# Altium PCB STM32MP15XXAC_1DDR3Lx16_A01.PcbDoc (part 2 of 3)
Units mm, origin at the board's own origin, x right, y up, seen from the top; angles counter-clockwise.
Board outline 89 x 120 mm, 4 copper layers (Top Layer, Signal Layer 1, Signal Layer 2, Bottom Layer), stack 1.571 mm thick; 133 components, 92 nets, 915 pads, 400 vias.
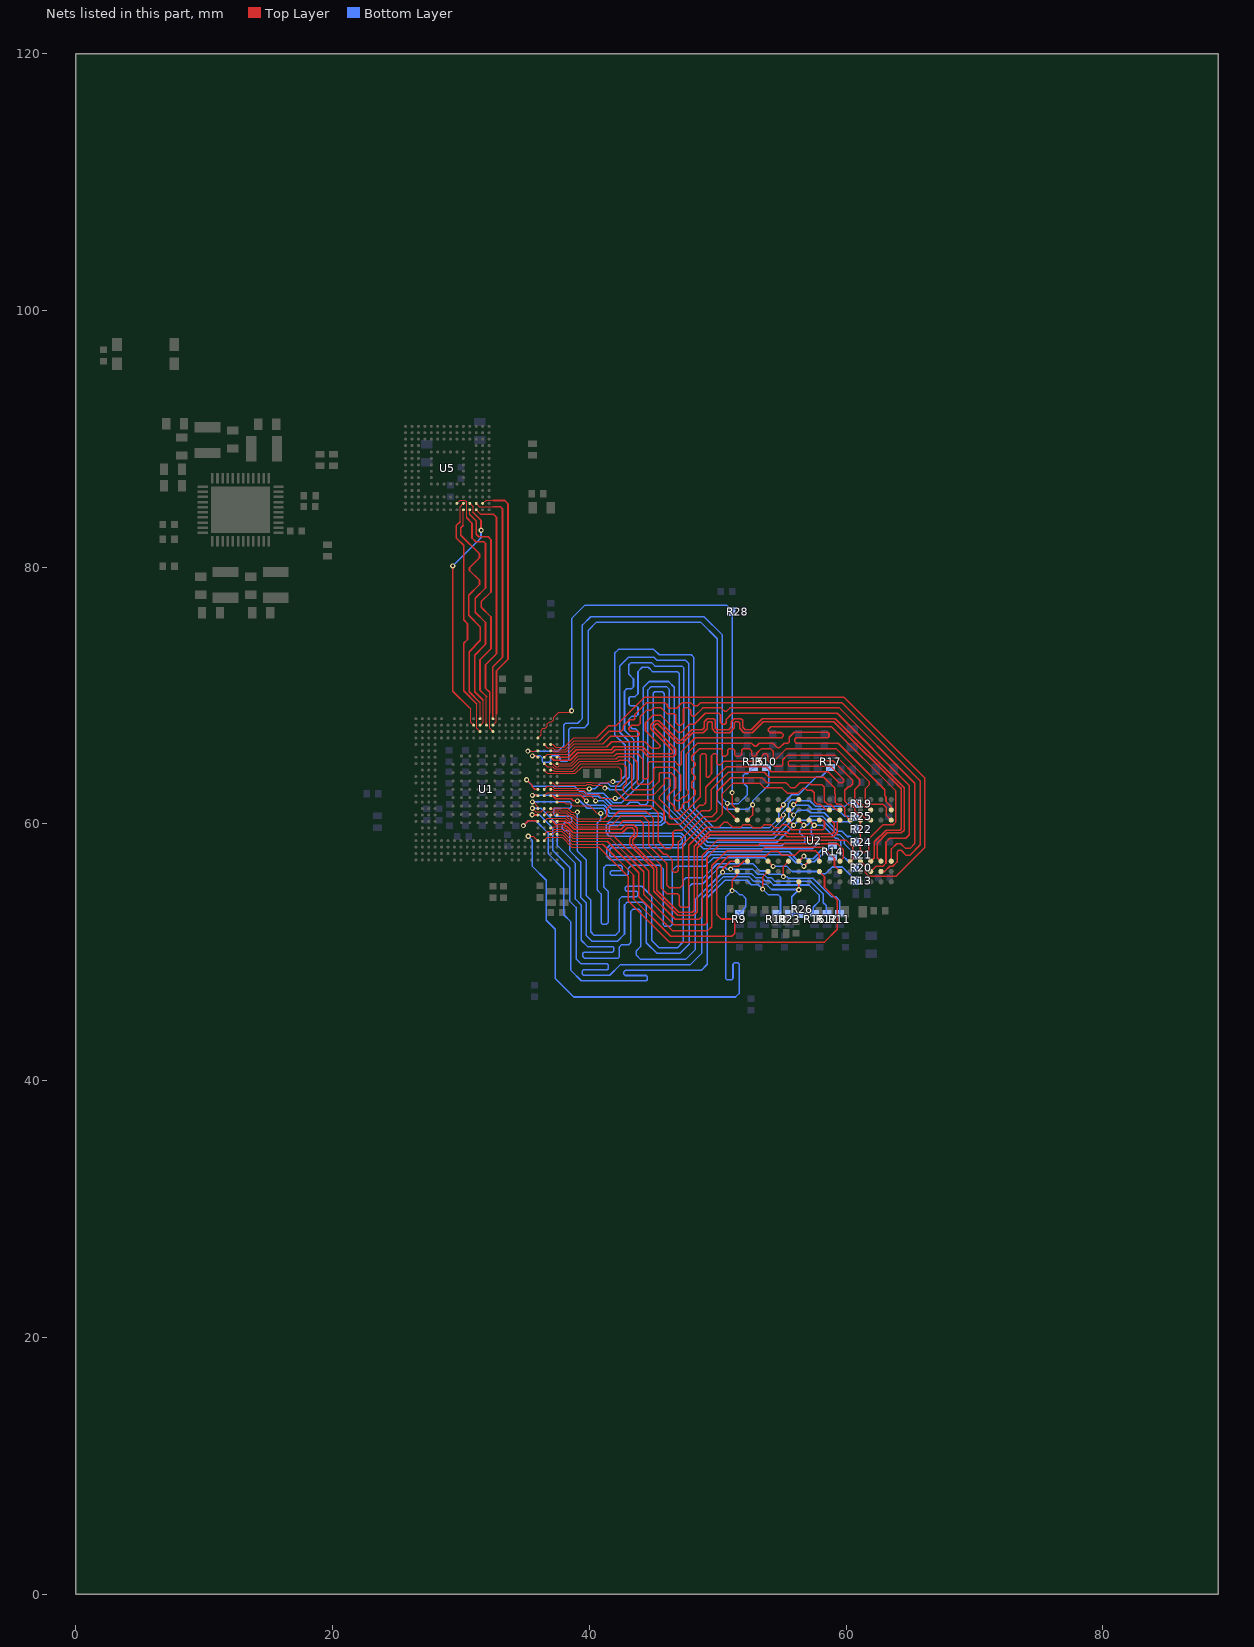
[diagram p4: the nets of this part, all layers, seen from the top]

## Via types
v1: diameter 0.4, hole 0.2, Top Layer to Bottom Layer, tented both sides, 241 vias
v2: diameter 0.6, hole 0.3, Top Layer to Bottom Layer, tented both sides, 81 vias
v3: diameter 0.25, hole 0.1, Top Layer to Signal Layer 1, tented top, 72 vias
v4: diameter 0.25, hole 0.1, Top Layer to Signal Layer 1, tented both sides, 6 vias

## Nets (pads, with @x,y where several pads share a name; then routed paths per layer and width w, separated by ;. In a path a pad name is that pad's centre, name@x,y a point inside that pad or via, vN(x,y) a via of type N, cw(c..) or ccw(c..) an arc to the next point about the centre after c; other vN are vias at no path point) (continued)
DDR_A8: R9.1 U1.Y20 U2.T8 | length 44.1
  Top Layer w0.09: v1(35.25,59.05) 35.65,59.05 U1.Y20@36,58.7
  Top Layer w0.12: v1(51.135,54.81) 51.135,55.634 51.525,56.024 U2.T8@51.525,56.3
  Bottom Layer w0.12: v1(35.25,59.05) 35.55,58.75 35.55,56.725 36.65,55.625 36.65,52.5 37.35,51.8 37.35,47.975 38.8,46.525 51.4,46.525 51.675,46.8 51.675,49.1 51.575,49.2 51.325,49.2 51.2,49.075 51.2,47.975 51.1,47.875 50.725,47.875 50.625,47.975 50.625,54.3 51.045,54.72 v1(51.135,54.81) 51.39,54.81 51.7,54.5 51.9,54.5 52.2,54.2 52.2,53.54 R9.1@51.705,53.045 R9.1@51.555,53.195
DDR_A9: R10.1 U1.G20 U2.R3 | length 47.2
  Top Layer w0.12: v1(35.575,65.3) 35.9,65.3 U1.G20@36,65.2 ; U2.R3@52.325,60.3 52.725,60.7 v1(52.725,61.5)
  Bottom Layer w0.12: v1(35.575,65.3) 36.2,65.3 36.325,65.175 36.325,64.9 36.4,64.825 36.9,64.825 37,64.925 37,65.225 37.1,65.325 37.6,65.325 37.725,65.2 37.725,64.975 37.825,64.875 38.25,64.875 38.4,65.025 38.4,67.35 38.55,67.5 39.625,67.5 39.925,67.8 39.925,75.075 40.575,75.725 48.675,75.725 49.975,74.425 49.975,61.825 50.65,61.15 52.375,61.15 v1(52.725,61.5) 52.725,61.79 54,63.065 54,64.2 R10.1@53.8,64.4
DDR_A10: R11.1 U1.R22 U2.L7 | length 49.9
  Top Layer w0.09: U1.R22@37,61.2 37.169,61.2 37.249,61.28 37.8,61.28 37.87,61.21 38.34,61.21 38.625,60.925 v1(39.075,60.925)
  Top Layer w0.12: v1(55.125,55.9) 55.125,56.7 U2.L7@55.525,57.1
  Bottom Layer w0.12: v1(39.075,60.925) 39.075,57.9 39.775,57.2 39.775,54.425 40.125,54.075 40.125,51.6 40.4,51.325 42.025,51.325 42.325,51.625 42.325,54.125 42.55,54.35 43.7,54.35 43.8,54.45 43.8,54.65 43.7,54.75 42.9,54.75 42.8,54.85 42.8,55.05 42.9,55.15 44.1,55.15 44.875,54.375 44.875,50.925 45.45,50.35 46.85,50.35 47.325,50.825 47.325,55.6 47.55,55.825 48.9,55.825 49.975,56.9 52.75,56.9 53.31,56.34 53.735,56.34 54,56.075 54.95,56.075 v1(55.125,55.9) 55.4,55.9 55.525,55.775 57.425,55.775 58.875,54.325 59.205,54.325 59.53,54 59.53,53.12 R11.1@59.455,53.045
DDR_A11: R12.1 U1.R20 U2.R7 | length 52.1
  Top Layer w0.09: v1(35.575,61.725) 35.636,61.725 36,61.361 U1.R20@36,61.2
  Top Layer w0.12: v1@51.015,56.42 v1@51.015,56.424 ; v1(51.015,56.49) 51.245,56.72 51.654,56.72 52.034,57.1 U2.R7@52.325,57.1
  Bottom Layer w0.12: v1(35.575,61.725) 38.475,61.725 38.6,61.6 38.6,61.325 38.5,61.225 37.325,61.225 37.225,61.125 37.225,60.775 37.4,60.6 38.525,60.6 38.65,60.475 38.65,60.2 38.55,60.1 38.075,60.1 37.9,59.925 37.9,59.65 38.075,59.475 38.375,59.475 38.5,59.35 38.5,57.9 39.35,57.05 39.35,54.275 39.775,53.85 39.775,51.325 40.225,50.875 42.2,50.875 42.75,51.425 42.75,53.7 42.95,53.9 44.2,53.9 44.45,53.65 44.45,50.75 45.275,49.925 47.075,49.925 47.8,50.65 47.8,55.125 48.025,55.35 48.85,55.35 50.15,56.65 50.55,56.65 50.71,56.49 v1(51.015,56.49) 52.71,56.49 53.125,56.075 53.6,56.075 53.85,55.825 54.175,55.825 54.475,55.525 57.25,55.525 58.23,54.545 58.23,53.87 58.455,53.645 R12.1@58.455,53.045
DDR_A12: R13.1 U1.P23 U2.N7 | length 51.2
  Top Layer w0.09: U1.P23@37.5,61.7 38.075,61.7 38.2,61.575 38.575,61.575 38.71,61.44 40.048,61.44 40.52,60.968 40.52,60.93 40.625,60.825 v1(40.9,60.825)
  Top Layer w0.12: U2.N7@53.925,57.1 v1(54.325,56.7)
  Bottom Layer w0.12: v1(40.9,60.825) 40.9,60.35 40.625,60.075 40.625,54.85 40.925,54.55 40.925,52.3 41.05,52.175 41.325,52.175 41.475,52.325 41.475,54.75 41.125,55.1 41.125,56.6 41.3,56.775 42.475,56.775 42.575,56.675 42.575,56.475 42.475,56.375 41.75,56.375 41.65,56.275 41.65,56.1 41.75,56 42.925,56 43.05,56.125 43.05,56.55 43.275,56.775 45.5,56.775 45.75,56.525 45.75,52.175 45.9,52.025 46.325,52.025 46.45,52.15 46.45,56.375 46.8,56.725 49.025,56.725 49.675,57.375 53.65,57.375 54.18,56.845 v1(54.325,56.7) 55.4,56.7 55.8,56.3 57.75,56.3 57.925,56.125 58.4,56.125 58.925,56.65 59.7,56.65 R13.1@60.755,55.595
DDR_A13: R15.1 U1.F20 U2.T3 | length 45.6
  Top Layer w0.09: v1(35.225,65.675) 35.25,65.7 35.437,65.7 35.482,65.655 35.768,65.655 35.813,65.7 U1.F20@36,65.7
  Top Layer w0.12: v1(50.765,61.61) 50.765,61.06 U2.T3@51.525,60.3
  Bottom Layer w0.09: v1(35.225,65.675) 35.245,65.655 35.92,65.655
  Bottom Layer w0.12: 35.92,65.655 37.555,65.655 38,66.1 38,67.7 38.15,67.85 39.1,67.85 39.475,68.225 39.475,75.5 40.125,76.15 48.95,76.15 50.35,74.75 50.35,62.025 v1(50.765,61.61) ; v1@50.665,61.59 51.625,61.59 52.3,62.265 52.3,62.9 52,63.2 52,63.8 52.1,63.9 52.3,63.9 R15.1@52.8,64.4
DDR_A14: R16.1 U1.R21 U2.T7 | length 54.1
  Top Layer w0.09: 35.725,61.075 35.85,60.95 36.25,60.95 U1.R21@36.5,61.2
  Top Layer w0.12: v1(50.395,56.25) 50.395,56.51 50.985,57.1 U2.T7@51.525,57.1
  Bottom Layer w0.12: v1(35.575,61.225) 36.25,61.225 37.525,59.95 37.525,58.325 38.925,56.925 38.925,54.15 39.375,53.7 39.375,50.95 39.875,50.45 41.85,50.45 41.925,50.375 41.925,50.125 41.825,50.025 39.6,50.025 39.5,49.925 39.5,49.675 39.625,49.55 42.25,49.55 42.35,49.65 42.35,50.425 42.525,50.6 43.075,50.6 43.225,50.75 43.225,53.175 43.425,53.375 43.85,53.375 44,53.225 44,50.45 43.675,50.125 43.675,49.775 44,49.45 47.5,49.45 48.275,50.225 48.275,54.13 v1(50.395,56.25) 50.52,56.125 52.65,56.125 52.95,55.825 53.425,55.825 53.675,55.575 54.025,55.575 54.35,55.25 57.125,55.25 57.905,54.47 57.905,53.97 57.455,53.52 R16.1@57.455,53.045
DDR_BA0: R17.1 U1.L23 U2.M2 | length 48
  Top Layer w0.09: U1.L23@37.5,63.2 39.697,63.2 39.762,63.265 40.188,63.265 40.253,63.2 41.4,63.2 41.5,63.3 v1(41.85,63.3)
  Top Layer w0.12: U2.M2@54.725,61.1 v1(55.125,61.5)
  Bottom Layer w0.12: v1(41.85,63.3) 42.35,63.3 42.8,63.75 42.8,66.125 41.975,66.95 41.975,73.3 42.275,73.6 45.025,73.6 45.45,73.175 47.95,73.175 48.125,73 48.125,61.3 49.7,59.725 54.05,59.725 54.75,60.425 54.75,60.975 55.125,61.35 v1(55.125,61.5) 55.125,61.625 55.775,62.275 56.3,62.275 57.7,63.675 58.075,63.675 R17.1@58.8,64.4
DDR_BA1: R18.1 U1.U20 U2.N8 | length 45.5
  Top Layer w0.12: v1(34.875,59.875) 35.26,60.26 35.749,60.26 35.809,60.2 U1.U20@36,60.2 ; v1@53.505,54.939 53.505,55.88 U2.N8@53.925,56.3
  Bottom Layer w0.12: v1(34.875,59.875) 35.26,60.26 35.84,60.26 36.8,59.3 36.8,57.7 38.025,56.475 38.025,52.925 38.575,52.375 38.575,48.6 39.375,47.8 44.45,47.8 44.525,47.875 44.525,48.125 44.45,48.2 42.8,48.2 42.7,48.3 42.7,48.5 42.8,48.6 48.725,48.6 49.2,49.075 49.2,54.25 50.575,55.625 52.275,55.625 52.625,55.275 53.16,55.275 v1(53.505,54.93) 53.935,54.5 54.7,54.5 54.9,54.3 54.9,53.24 R18.1@54.705,53.045
DDR_BA2: R19.1 U1.M21 U2.M3 | length 49.6
  Top Layer w0.09: U1.M21@36.5,62.7 36.75,62.95 37.135,62.95 37.295,62.79 39.885,62.79 39.95,62.725 v1@40,62.725
  Top Layer w0.12: U2.M3@54.725,60.3 v1@55.105,60.68
  Bottom Layer w0.12: v1(40,62.735) 40.435,62.735 40.875,63.175 41.466,63.175 41.701,62.94 41.999,62.94 42.005,62.945 ; 42,62.95 42.425,62.95 43.125,63.65 43.125,66.4 42.375,67.15 42.375,72.3 43.075,73 45.025,73 45.275,72.75 47.5,72.75 47.75,72.5 47.75,61.225 49.55,59.425 54.125,59.425 55.125,60.425 v1(55.125,60.7) 55.125,60.925 55.5,61.3 55.5,61.6 55.8,61.9 56.1,61.9 56.18,61.82 57.18,61.82 57.6,61.4 59.955,61.4 60.225,61.67 60.68,61.67 R19.1@60.755,61.595
DDR_CASN: R21.1 U1.N20 U2.K3 | length 49.6
  Top Layer w0.09: v1(35.575,62.225) v1@35.6,62.2
  Top Layer w0.12: v1(35.575,62.225) 35.975,62.225 U1.N20@36,62.2 ; U2.K3@56.325,60.3 v1(56.725,59.9)
  Bottom Layer w0.12: v1(35.575,62.225) 39.375,62.225 39.435,62.165 40.71,62.165 40.825,62.05 41.169,62.05 41.794,61.425 42.875,61.425 43.15,61.7 43.8,61.7 44,61.5 44.4,61.5 44.575,61.675 44.575,70.441 44.834,70.7 46.016,70.7 46.25,70.466 46.25,61.175 49.125,58.3 55,58.3 55.2,58.5 56.7,58.5 56.8,58.6 56.8,58.9 56.4,59.3 56.4,59.575 v1(56.725,59.9) 56.975,59.9 57.375,60.3 58.175,60.3 59.325,59.15 59.53,59.15 59.88,58.8 59.88,58.445 60.73,57.595 R21.1@60.755,57.595
DDR_CKE: R23.1 R26.2 U1.T20 U2.K9 | length 45.4
  Top Layer w0.12: v1(35.55,60.725) 35.575,60.7 U1.T20@36,60.7 ; v1(56.325,54.88) U2.K9@56.325,55.5
  Bottom Layer w0.12: v1(35.55,60.725) 36.125,60.725 37.15,59.7 37.15,57.95 38.475,56.625 38.475,54 38.975,53.5 38.975,49.5 39.35,49.125 41.375,49.125 41.475,49.025 41.475,48.725 41.4,48.65 39.55,48.65 39.45,48.55 39.45,48.325 39.55,48.225 41.6,48.225 42.4,49.025 47.85,49.025 48.775,49.95 48.775,54.225 50.425,55.875 52.475,55.875 52.8,55.55 53.325,55.55 53.55,55.325 53.775,55.325 54.2,54.9 56.305,54.9 v1(56.325,54.88) 55.78,54.335 R23.1@55.78,53.045 ; R23.1@55.705,53.045 R23.1@55.78,53.045 ; R26.2@56.58,52.92 56.455,53.045 R23.1@55.78,53.045
DDR_CLK_N: R14.2 U1.N23 U2.K7 | length 46.7
  Top Layer w0.1: U1.N23@37.5,62.2 39.375,62.2 v1(39.775,61.8) ; U2.K7@56.325,57.1 v1(56.725,57.5)
  Bottom Layer w0.1: v1(39.775,61.8) 39.775,61.625 39.95,61.45 41.17,61.45 41.53,61.09 41.53,60.92 41.6,60.85 45.625,60.85 45.905,60.57 45.905,60.18 45.62,59.895 41.645,59.895 41.555,59.805 41.555,59.395 41.675,59.275 47.175,59.275 47.475,58.975 47.475,58.45 47.175,58.15 41.725,58.15 41.605,58.03 41.605,57.57 41.725,57.45 48.95,57.45 49.325,57.825 55.575,57.825 56.175,57.225 56.45,57.225 56.65,57.425 v1(56.725,57.5) 56.94,57.285 57.435,57.285 58.125,57.975 58.56,57.975 58.88,58.295 R14.2@58.955,58.295
DDR_CLK_P: R14.1 U1.N22 U2.J7 | length 47.3
  Top Layer w0.1: U1.N22@37,62.2 37.15,62.2 37.4,61.95 37.605,61.95 37.625,61.97 38.605,61.97 38.775,61.8 v1(39.075,61.8) ; v1(56.725,56.7) U2.J7@57.125,57.1
  Bottom Layer w0.1: v1(39.075,61.8) 39.275,61.8 39.855,61.22 41.075,61.22 41.3,60.995 41.3,60.825 41.505,60.62 45.53,60.62 45.675,60.475 45.675,60.275 45.525,60.125 41.55,60.125 41.325,59.9 41.325,59.3 41.58,59.045 47.08,59.045 47.245,58.88 47.245,58.545 47.08,58.38 41.63,58.38 41.375,58.125 41.375,57.475 41.63,57.22 49.045,57.22 49.42,57.595 55.48,57.595 56.1,56.975 56.45,56.975 56.58,56.845 v1(56.725,56.7) 57.08,57.055 57.53,57.055 58.215,57.74 58.56,57.74 58.905,57.395 R14.1@58.955,57.395
DDR_CSN: R22.1 U1.M22 U2.L2 | length 49.2
  Top Layer w0.09: U1.M22@37,62.7 37.145,62.7 37.225,62.62 39.567,62.62 39.857,62.33 40.695,62.33 41.025,62 v1(42.025,62)
  Top Layer w0.12: U2.L2@55.525,61.1 v1(55.925,60.7)
  Bottom Layer w0.12: v1(42.025,62) 42.35,62 43.8,63.45 43.8,67.225 43.6,67.425 43.35,67.425 43.1,67.675 43.1,68.175 43.3,68.375 43.65,68.375 43.8,68.525 43.8,69.075 43.675,69.2 43.225,69.2 43.1,69.325 43.1,69.825 43.2,69.925 43.575,69.925 43.8,70.15 43.8,71.875 44.125,72.2 44.6,72.2 44.925,71.875 46.85,71.875 47.025,71.7 47.025,61.125 49.275,58.875 54.375,58.875 55.925,60.425 v1(55.925,60.7) 56.3,61.075 57.025,61.075 57.225,60.875 58.3,60.875 58.987,60.187 60.162,60.187 R22.1@60.755,59.595
DDR_DQ0: U1.E22 U2.D7 | length 45.6
  Top Layer w0.09: U1.E22@37,66.2 37.15,66.2 37.39,65.96 38.06,65.96 38.8,66.7 40.55,66.7
  Top Layer w0.12: 40.55,66.7 41.51,67.66 42.085,67.66 44.305,69.88 59.837,69.88 66.15,63.567 66.15,58.196 63.874,55.92 61.796,55.92 61.503,56.213 61.503,56.744 61.148,57.1 U2.D7@61.125,57.1
DDR_DQ1: U1.F22 U2.A7 | length 45.3
  Top Layer w0.09: U1.F22@37,65.7 37.169,65.7 37.249,65.62 38.22,65.62 38.85,66.25 41.075,66.25
  Top Layer w0.12: 41.075,66.25 41.645,66.82 43.795,66.82 43.9,66.925 43.9,67.064 43.739,67.225 43.2,67.225 43.075,67.35 43.075,67.456 43.319,67.7 43.84,67.7 43.965,67.825 43.965,68.346 44.494,68.875 44.825,68.875 44.99,69.04 45.609,69.04 46.049,68.6 46.65,68.6 46.749,68.501 46.749,67.9 46.975,67.675 47.134,67.675 47.342,67.883 47.342,68.958 47.424,69.04 47.725,69.04 47.9,68.865 47.9,68.525 48.023,68.402 48.223,68.402 48.861,69.04 50.274,69.04 50.519,68.794 50.721,68.794 50.966,69.04 59.489,69.04 65.355,63.174 65.355,58.48 64.975,58.1 64.635,58.1 64.265,58.47 63.945,58.47 63.535,58.06 U2.A7@63.535,57.1
DDR_DQ2: U1.H21 U2.A3 | length 45.7
  Top Layer w0.09: U1.H21@36.5,64.7 36.75,64.45 37.17,64.45 37.33,64.29 38.69,64.29 39.275,64.875 42.225,64.875
  Top Layer w0.12: 42.225,64.875 42.325,64.975 42.936,64.975 43.32,64.591 43.32,62.775 43.41,62.685 44.823,62.685 45.44,63.302 45.44,63.91 45.525,63.995 46.374,63.995 46.72,63.649 46.72,62.776 46.097,62.153 46.097,61.91 46.665,61.342 46.665,61.1 46.74,61.025 46.968,61.025 47.243,61.3 47.243,61.474 47.459,61.691 47.634,61.691 48.24,62.297 48.24,62.625 47.995,62.87 47.995,63.25 48.24,63.495 48.24,63.725 47.995,63.97 47.995,64.275 48.24,64.52 48.24,64.755 47.995,65 47.995,65.269 48.601,65.875 50.25,65.875 50.37,65.755 50.37,65.37 50.45,65.29 50.64,65.29 50.775,65.425 50.775,65.75 50.9,65.875 51.2,65.875 51.325,65.75 51.325,65.39 51.425,65.29 51.74,65.29 51.875,65.425 51.875,65.775 51.975,65.875 52.475,65.875 52.65,65.7 52.65,65.4 52.76,65.29 52.95,65.29 53.055,65.395 53.055,65.504 53.426,65.875 54.125,65.875 54.325,65.675 54.325,65.175 54.4,65.1 54.587,65.1 55.362,65.875 59.231,65.875 61.8,63.306 61.8,63.04 61.485,62.725 61.485,61.831 61.776,61.54 62.887,61.54 63.125,61.302 63.125,60.7 U2.A3@63.525,60.3
DDR_DQ3: U1.E21 U2.B8 | length 44.1
  Top Layer w0.09: U1.E21@36.5,66.2 36.75,65.95 37.16,65.95 37.32,65.79 38.14,65.79 38.825,66.475 40.8,66.475
  Top Layer w0.12: 40.8,66.475 41.565,67.24 42.495,67.24 42.655,67.4 42.655,67.63 43.15,68.125 43.47,68.125 43.545,68.2 43.545,68.52 44.485,69.46 45.9,69.46 46.075,69.285 46.075,69.168 46.223,69.02 46.81,69.02 47.25,69.46 47.899,69.46 48.154,69.204 48.431,69.204 48.687,69.46 59.663,69.46 65.775,63.348 65.775,58.375 64.975,57.575 64.675,57.575 64.3,57.95 64.1,57.95 63.975,57.825 63.975,57.041 63.644,56.71 63.415,56.71 63.005,56.3 U2.B8@62.725,56.3
DDR_DQ4: U1.J21 U2.C3 | length 46.2
  Top Layer w0.09: U1.J21@36.5,64.2 36.75,63.95 38.925,63.95 39.45,64.475 42.248,64.475 42.48,64.243
  Top Layer w0.12: 42.48,64.243 42.48,63.355 42.05,62.925 42.05,62.6 42.805,61.845 44.974,61.845 45.825,60.994 45.825,60.351 46.201,59.975 47.106,59.975 48.576,61.445 48.87,61.445 49.08,61.655 49.08,62.858 50.67,64.448 51.95,64.448 ; 51.95,64.45 53.801,64.45 54.181,64.07 58.605,64.07 59.475,63.2 59.7,63.2 59.825,63.325 59.825,63.475 58.8,64.5 55.6,64.5 55.5,64.6 55.5,64.825 55.6,64.925 58.993,64.925 60.534,63.384 60.534,63.133 60.311,62.91 60.176,62.91 59.9,62.634 59.9,61.785 60.2,61.485 60.449,61.485 60.685,61.249 60.685,61.031 61.056,60.66 61.274,60.66 61.485,60.449 61.485,60.44 61.494,60.44 61.634,60.3 U2.C3@61.925,60.3
DDR_DQ5: U1.J22 U2.C2 | length 45.2
  Top Layer w0.09: U1.J22@37,64.2 37.18,64.2 37.26,64.12 38.795,64.12 39.35,64.675 42.642,64.675 42.775,64.542
  Top Layer w0.12: 42.775,64.542 42.9,64.417 42.9,63.181 42.634,62.916 42.634,62.609 42.979,62.265 44.997,62.265 45.86,63.128 45.86,63.485 45.95,63.575 46.2,63.575 46.3,63.475 46.3,62.95 45.444,62.094 45.444,61.969 46.245,61.168 46.245,60.525 46.375,60.395 46.932,60.395 48.66,62.123 48.66,65.34 48.775,65.455 49.02,65.455 49.1,65.375 49.1,63.725 49.189,63.636 49.264,63.636 ; 49.275,63.647 49.525,63.897 49.525,65.33 49.65,65.455 49.87,65.455 49.95,65.375 49.95,64.7 50.025,64.625 50.253,64.625 50.498,64.87 53.325,64.87 53.475,65.02 53.475,65.33 53.6,65.455 53.825,65.455 53.905,65.375 53.905,64.94 54.355,64.49 54.975,64.49 55.08,64.595 55.08,64.999 55.451,65.37 59.142,65.37 61.065,63.447 61.065,63.07 60.695,62.7 60.695,61.821 60.976,61.54 61.23,61.54 61.23,61.535 61.445,61.32 61.705,61.32 U2.C2@61.925,61.1
DDR_DQ6: U1.H22 U2.A2 | length 46.3
  Top Layer w0.09: U1.H22@37,64.7 37.161,64.7 37.401,64.46 37.599,64.46 37.669,64.53 38.655,64.53 39.2,65.075 42.1,65.075
  Top Layer w0.12: 42.1,65.075 42.25,65.225 43.325,65.225 43.74,64.81 43.74,63.19 43.825,63.105 44.649,63.105 45.02,63.476 45.02,64.285 45.15,64.415 46.548,64.415 47.14,63.823 47.14,62.602 46.675,62.138 46.675,61.925 46.776,61.825 47,61.825 47.288,62.112 47.462,62.112 47.723,62.374 47.723,62.548 47.575,62.696 47.575,65.443 48.427,66.295 52.649,66.295 52.894,66.05 53.007,66.05 53.252,66.295 54.299,66.295 54.644,65.95 54.843,65.95 55.188,66.295 55.475,66.295 55.575,66.395 55.575,66.75 55.975,67.15 58.6,67.15 58.675,67.075 58.675,66.8 58.6,66.725 56.125,66.725 56,66.6 56,66.425 56.13,66.295 59.405,66.295 63.025,62.675 63.025,62.2 63.115,62.11 63.115,61.76 63.525,61.35 U2.A2@63.525,61.1
DDR_DQ7: U1.G21 U2.C8 | length 46.6
  Top Layer w0.09: U1.G21@36.5,65.2 36.74,65.44 38.315,65.44 38.9,66.025 41.375,66.025
  Top Layer w0.12: 41.375,66.025 41.75,66.4 44.355,66.4 44.87,65.885 45.375,65.885 45.535,66.045 45.535,66.11 44.385,67.26 44.385,67.885 44.955,68.455 45.6,68.455 46.894,67.161 47.214,67.161 47.818,67.765 48.18,67.765 49.035,68.62 50.1,68.62 50.225,68.495 50.225,67.9 50.36,67.765 50.55,67.765 50.665,67.88 50.665,68.145 51.14,68.62 59.315,68.62 64.935,63 64.935,59.17 64.655,58.89 63.4,58.89 63.115,58.605 63.115,56.96 62.855,56.7 62.325,56.7 U2.C8@61.925,56.3
DDR_DQ8: U1.T21 U2.E3 | length 34.2
  Top Layer w0.09: U1.T21@36.5,60.7 36.75,60.95 37.16,60.95 37.32,61.11 37.73,61.11 37.8,61.04 38.27,61.04 38.555,60.755 38.72,60.755 39.075,60.4 41.15,60.4
  Top Layer w0.12: 41.15,60.4 41.375,60.625 41.375,61.175 41.625,61.425 44.8,61.425 45.375,60.85 45.375,58.65 45.95,58.075 46.3,58.075 46.525,58.3 46.525,59.375 46.675,59.525 47.25,59.525 48.75,61.025 49.35,61.025 49.5,61.175 49.5,62.684 50.844,64.028 53.628,64.028 54.007,63.65 58.27,63.65 59.12,62.8 59.12,62.39 59.145,62.365 59.145,61.71 59.315,61.54 59.609,61.54 59.915,61.234 59.915,60.71 U2.E3@60.325,60.3
DDR_DQ9: U1.U21 U2.H3 | length 35
  Top Layer w0.09: U1.U21@36.5,60.2 36.75,60.45 38.138,60.45 38.343,60.245 38.465,60.245 38.91,59.8 42.2,59.8
  Top Layer w0.12: 42.2,59.8 42.65,60.25 44,60.25 44.225,60.025 44.225,58.175 45.625,56.775 45.625,55 46.075,54.55 46.9,54.55 47,54.45 47,53.675 47.15,53.525 47.675,53.525 47.75,53.6 47.75,58.35 49.15,59.75 50.1,59.75 50.475,60.125 50.775,60.125 51.15,59.75 51.8,59.75 51.979,59.929 52.525,59.929 52.729,59.725 53.4,59.725 53.604,59.929 54.2,59.929 54.404,59.725 54.85,59.725 55.054,59.929 55.387,59.929 55.776,59.54 58.19,59.54 58.325,59.675 58.325,60.175 58.225,60.275 57.95,60.275 U2.H3@57.925,60.3
DDR_DQ10: U1.T22 U2.F2 | length 34.1
  Top Layer w0.09: U1.T22@37,60.7 37.15,60.7 37.39,60.94 37.599,60.94 37.669,60.87 38.199,60.87 38.484,60.585 38.64,60.585 39.025,60.2 41.5,60.2
  Top Layer w0.12: 41.5,60.2 42.3,61 44.425,61 45,60.425 45,58.45 45.8,57.65 46.025,57.65 46.45,57.225 46.45,56.4 46.6,56.25 46.8,56.25 46.95,56.4 46.95,58.6 48.925,60.575 49.575,60.575 49.925,60.925 49.925,62.515 51.015,63.605 53.451,63.605 ; 53.454,63.608 53.833,63.23 55.305,63.23 55.725,62.81 56.015,62.81 56.4,63.195 57.154,63.195 57.299,63.05 58.139,63.05 58.315,62.874 58.315,61.77 58.555,61.53 58.819,61.53 59.249,61.1 U2.F2@59.525,61.1
DDR_DQ11: U1.W21 U2.F7 | length 34.4
  Top Layer w0.09: U1.W21@36.5,59.2 36.75,59.45 37.16,59.45 37.32,59.61 37.918,59.61 38.033,59.495 38.08,59.495 38.7,58.875 41.65,58.875
  Top Layer w0.12: 41.65,58.875 44.25,56.275 44.25,54.5 46.6,52.15 49,52.15 49.175,52.325 49.175,57.425 50.08,58.33 53.165,58.33 53.295,58.46 59.34,58.46 59.775,58.025 59.775,57.35 U2.F7@59.525,57.1
DDR_DQ12: U1.W23 U2.H7 | length 33.9
  Top Layer w0.09: U1.W23@37.5,59.2 37.545,59.155 37.92,59.155 38.65,58.425 41.05,58.425
  Top Layer w0.12: 41.05,58.425 43.45,56.025 43.45,54.15 46.35,51.25 51.1,51.25 51.35,51.5 51.35,52.35 51.1,52.6 50.275,52.6 49.925,52.95 49.925,56.575 50.835,57.485 53.75,57.485 54.125,57.86 54.725,57.86 55.015,57.57 56.035,57.57 56.368,57.903 57.652,57.903 57.925,57.58 U2.H7@57.925,57.1
DDR_DQ13: U1.T23 U2.G2 | length 33.9
  Top Layer w0.09: U1.T23@37.5,60.7 38.129,60.7 38.414,60.415 38.535,60.415 38.95,60 41.85,60
  Top Layer w0.12: 41.85,60 42.475,60.625 44.2,60.625 44.625,60.2 44.625,58.35 46.025,56.95 46.025,55.275 46.275,55.025 47.05,55.025 47.3,55.275 47.3,58.425 49.1,60.225 49.825,60.225 50.345,60.745 50.345,62.341 51.189,63.185 53.284,63.185 53.659,62.81 55.023,62.81 55.455,62.378 56.218,62.378 56.615,62.775 56.825,62.775 56.97,62.63 57.335,62.63 57.535,62.43 57.535,61.75 57.745,61.54 58.015,61.54 58.455,61.1 U2.G2@58.725,61.1
DDR_DQ14: U1.W22 U2.F8 | length 33.5
  Top Layer w0.09: U1.W22@37,59.2 37.161,59.2 37.401,59.44 37.847,59.44 37.962,59.325 38,59.325 38.675,58.65 41.4,58.65
  Top Layer w0.12: 41.4,58.65 43.85,56.2 43.85,54.325 46.475,51.7 49.25,51.7 49.55,52 49.55,56.75 50.705,57.905 53.38,57.905 53.65,58.175 58.25,58.175 59.105,57.32 59.105,56.72 U2.F8@59.525,56.3
DDR_DQ15: U1.Y21 U2.H8 | length 32.9
  Top Layer w0.09: U1.Y21@36.5,58.7 36.75,58.95 37.885,58.95 38.635,58.2 40.625,58.2
  Top Layer w0.12: 40.625,58.2 40.75,58.2 43.05,55.9 43.05,53.975 46.225,50.8 58.325,50.8 59.325,51.8 59.325,54.08 58.325,55.08 58.325,55.9 U2.H8@57.925,56.3
DDR_DQM0: U1.H23 U2.D3 | length 45.1
  Top Layer w0.09: U1.H23@37.5,64.7 38.55,64.7 39.15,65.3 41.95,65.3
  Top Layer w0.12: 41.95,65.3 42.125,65.475 43.775,65.475 44.16,65.09 44.16,63.615 44.25,63.525 44.475,63.525 44.6,63.65 44.6,64.75 44.685,64.835 46.722,64.835 46.982,64.575 47.08,64.575 47.155,64.65 47.155,65.617 48.253,66.715 54.99,66.715 55.125,66.85 55.125,66.95 54.95,67.125 54.075,67.125 53.95,67.25 53.95,67.375 54.145,67.57 58.88,67.57 63.885,62.565 63.885,60.151 63.674,59.94 62.874,59.94 61.775,58.841 61.775,57.95 61.675,57.85 61.3,57.85 61.125,58.025 U2.D3@61.125,60.3 ; U2.D3@61.105,60.343 U2.D3@61.128,60.32
DDR_DQM1: U1.V22 U2.E7 | length 34.3
  Top Layer w0.09: U1.V22@37,59.7 37.169,59.7 37.249,59.78 37.988,59.78 38.103,59.665 38.16,59.665 38.725,59.1 41.875,59.1
  Top Layer w0.12: 41.875,59.1 44.65,56.325 44.65,54.625 46.7,52.575 48.55,52.575 48.8,52.825 48.8,57.55 50,58.75 60,58.75 60.525,58.225 60.525,57.3 U2.E7@60.325,57.1
DDR_DQS0_N: U1.G23 U2.B7 | length 45.8
  Top Layer w0.1: U1.G23@37.5,65.2 38.4,65.2 38.98,65.78 41.705,65.78 41.93,66.005 44.17,66.005 44.7,65.475 46.445,65.475 46.515,65.545 46.515,65.71 44.795,67.43 44.795,67.715 45.125,68.045 45.43,68.045 46.945,66.53 47.163,66.53 47.988,67.355 48.805,67.355 48.945,67.495 48.945,67.95 49.205,68.21 49.7,68.21 49.815,68.095 49.815,67.51 49.97,67.355 50.85,67.355 51.075,67.58 51.075,67.975 51.31,68.21 51.815,68.21 51.95,68.075 51.95,67.55 52.145,67.355 52.605,67.355 53.46,68.21 59.145,68.21 64.525,62.83 64.525,59.52 64.305,59.3 63.23,59.3 62.445,58.515 62.445,57.38 U2.B7@62.725,57.1
DDR_DQS0_P: U1.G22 U2.C7 | length 45.9
  Top Layer w0.1: U1.G22@37,65.2 37.25,64.95 37.655,64.95 37.675,64.97 38.52,64.97 39.1,65.55 41.8,65.55 42.025,65.775 44.075,65.775 44.605,65.245 46.54,65.245 46.745,65.45 46.745,65.805 45.025,67.525 45.025,67.62 45.22,67.815 45.335,67.815 46.85,66.3 47.258,66.3 48.083,67.125 48.9,67.125 49.175,67.4 49.175,67.855 49.3,67.98 49.5,67.98 49.58,67.9 49.585,67.9 49.585,67.415 49.875,67.125 50.945,67.125 51.305,67.485 51.305,67.88 51.405,67.98 51.625,67.98 51.72,67.885 51.72,67.455 52.05,67.125 52.7,67.125 53.555,67.98 59.05,67.98 64.295,62.735 64.295,59.615 64.21,59.53 63.135,59.53 62.215,58.61 62.215,57.39 U2.C7@61.925,57.1
DDR_DQS1_N: U1.U23 U2.G3 | length 33.8
  Top Layer w0.1: U1.U23@37.5,60.2 38.141,60.2 38.271,60.07 38.355,60.07 38.85,59.575 42.5,59.575 42.855,59.93 43.445,59.93 43.725,59.65 43.725,59.125 43.375,58.775 43.375,58.475 45.25,56.6 45.25,54.85 46.975,53.125 48.025,53.125 48.175,53.275 48.175,58.25 49.33,59.405 55.37,59.405 55.525,59.25 58.925,59.25 59.075,59.4 59.075,60.05 58.825,60.3 U2.G3@58.725,60.3
DDR_DQS1_P: U1.U22 U2.F3 | length 34.6
  Top Layer w0.1: U1.U22@37,60.2 37.154,60.2 37.399,59.955 37.601,59.955 37.616,59.97 38.046,59.97 38.176,59.84 38.26,59.84 38.775,59.325 42.575,59.325 42.95,59.7 43.35,59.7 43.495,59.555 43.495,59.22 43.145,58.87 43.145,58.38 45.02,56.505 45.02,54.755 46.88,52.895 48.12,52.895 48.405,53.18 48.405,58.155 49.425,59.175 55.275,59.175 55.43,59.02 59.02,59.02 59.305,59.305 59.305,60.08 U2.F3@59.525,60.3
DDR_ODT: R25.1 U1.L22 U2.K1 | length 49
  Top Layer w0.09: U1.L22@37,63.2 37.161,63.2 37.401,62.96 37.599,62.96 37.602,62.963 37.605,62.96 37.675,63.03 39.767,63.03 39.832,63.095 40.118,63.095 40.183,63.03 40.995,63.03 v1(41.225,62.8)
  Top Layer w0.12: v1(55.925,61.5) U2.K1@56.325,61.9
  Bottom Layer w0.12: v1(41.225,62.8) 41.475,62.8 41.6,62.675 42.6,62.675 43.475,63.55 43.475,66.575 42.75,67.3 42.75,70.35 42.925,70.525 43.3,70.525 43.45,70.675 43.45,71.3 43.075,71.675 43.075,72.4 43.25,72.575 44.85,72.575 45.125,72.3 47.225,72.3 47.375,72.15 47.375,61.175 49.4,59.15 54.25,59.15 55.525,60.425 55.525,60.825 55.925,61.225 v1(55.925,61.5) 55.967,61.457 57.068,61.457 57.375,61.15 59.325,61.15 59.88,60.595 R25.1@60.755,60.595
DDR_RASN: R20.1 U1.N21 U2.J3 | length 49
  Top Layer w0.09: U1.N21@36.5,62.2 36.75,62.45 39.45,62.45 39.75,62.15 40.15,62.15 v1(40.5,61.8)
  Top Layer w0.1: U2.J3@57.105,60.314 U2.J3@57.106,60.312
  Top Layer w0.12: U2.J3@57.125,60.3 v1(57.525,59.9)
  Bottom Layer w0.12: v1(40.5,61.8) 41.122,61.8 41.772,61.15 44.775,61.15 44.975,61.35 44.975,70.175 45.1,70.3 45.7,70.3 45.85,70.15 45.85,61.125 48.9,58.075 57.375,58.075 57.8,58.5 57.8,58.9 57.7,59 57.5,59 57.3,59.2 57.3,59.675 v1(57.525,59.9) 58.175,59.9 59.2,58.875 59.355,58.875 59.58,58.65 59.58,57.695 60.33,56.945 60.455,56.945 60.755,56.645 R20.1@60.755,56.595
DDR_RESETN: R28.2 U1.D20 U2.T2 | length 39.9
  Top Layer w0.09: U1.D20@36,66.7 36.25,66.95 36.25,67.3 36.4,67.45 36.589,67.45 36.75,67.611 36.75,67.789 36.911,67.95 37.089,67.95 37.25,68.111 37.25,68.325 37.645,68.72 38.52,68.72 v1(38.625,68.825)
  Top Layer w0.12: v1(51.125,62.44) 51.125,61.5 U2.T2@51.525,61.1
  Bottom Layer w0.12: v1(38.625,68.825) 38.625,76 39.675,77.05 50.7,77.05 51.125,76.625 R28.2@51.125,76.55 51.125,66.525 v1(51.125,62.44)
DDR_WEN: R24.1 U1.M20 U2.L3 | length 48.8
  Top Layer w0.12: v1(35.125,63.45) 35.575,63 35.575,62.875 35.75,62.7 U1.M20@36,62.7 ; U2.L3@55.525,60.3 v1(55.925,59.9)
  Bottom Layer w0.12: v1(35.125,63.45) 35.65,62.925 38.875,62.925 39.25,62.55 39.55,62.55 39.725,62.375 40.159,62.375 40.169,62.385 41.131,62.385 41.876,61.64 42.49,61.64 44.2,63.35 44.2,70.631 44.669,71.1 46.181,71.1 46.625,70.656 46.625,61.175 49.225,58.575 54.6,58.575 v1(55.925,59.9) 56.325,60.3 56.95,60.3 57.245,60.595 58.18,60.595 59.325,59.45 59.675,59.45 60.1,59.025 60.325,59.025 R24.1@60.755,58.595
eMMC_SDIO2_D0: U1.C13 U5.A3 | length 19.1
  Top Layer w0.09: U5.A3@31.2,84.475 31.55,84.125 ; 32.25,68.625 32.25,67.45 U1.C13@32.5,67.2
  Top Layer w0.13: 31.55,84.125 32.55,84.125 32.775,83.9 32.775,73.25 31.925,72.4 31.925,70.575 32.25,70.25 32.25,68.625
eMMC_SDIO2_D1: U1.B12 U5.A4 | length 19.1
  Top Layer w0.09: 30.7,84.1 U5.A4@30.7,84.475 ; U1.B12@32,67.7 32,69.925
  Top Layer w0.13: 30.7,84.1 31.2,83.6 31.2,82.575 31.4,82.375 32.125,82.375 32.35,82.15 32.35,78.075 31.6,77.325 31.6,76.875 32.35,76.125 32.35,73.65 31.5,72.8 31.5,70.425 32,69.925
eMMC_SDIO2_D2: U1.A11 U5.A5 | length 19
  Top Layer w0.09: 30.2,83.275 U5.A5@30.2,84.475 ; U1.A11@31.5,68.2 31.5,69.45
  Top Layer w0.13: 30.2,83.275 30,83.075 30,82.5 31.45,81.05 31.45,80.725 30.675,79.95 30.675,79.75 31.45,78.975 31.45,78.65 30.625,77.825 30.625,76.25 31.525,75.35 31.525,74.3 30.65,73.425 30.65,70.3 31.5,69.45
eMMC_SDIO2_D3: U1.B13 U5.B2 | length 19.9
  Top Layer w0.09: U5.B2@31.7,84.975 31.725,84.975 31.965,85.215 32.51,85.215 32.525,85.2 ; U1.B13@32.5,67.7 32.75,67.95 32.75,68.6 ; 33.4,85.2 33.425,85.2
  Top Layer w0.13: 32.525,85.2 33.4,85.2 ; 32.775,68.6 32.775,71.941 33.675,72.841 33.675,84.95 33.425,85.2
eMMC_SDIO2_D4: U1.A13 U5.B3 | length 18.9
  Top Layer w0.09: U5.B3@31.2,84.975 31.2,84.965 31.45,84.715 32.515,84.715
  Top Layer w0.13: U1.A13@32.5,68.2 32.5,72.25 33.25,73 33.25,84.55 33.085,84.715 32.515,84.715
eMMC_SDIO2_D5: U1.B10 U5.B4 | length 19.2
  Top Layer w0.09: 30.65,69.075 30.76,68.965 30.76,67.94 U1.B10@31,67.7 ; U5.B4@30.7,84.975 30.95,84.725 30.95,84.275
  Top Layer w0.13: v1(29.375,80.1) 29.375,70.35 30.65,69.075 ; 30.95,84.275 31.575,83.65 v1(31.575,82.875)
  Bottom Layer w0.13: v1(29.375,80.1) 31.575,82.3 v1(31.575,82.875)
eMMC_SDIO2_D6: U1.C11 U5.B5 | length 19
  Top Layer w0.09: 29.95,83.55 29.95,84.725 U5.B5@30.2,84.975 U5.B5@30.2,84.965 ; 31.25,69.35 31.25,67.45 U1.C11@31.5,67.2
  Top Layer w0.13: 29.95,83.55 29.65,83.25 29.65,82.275 30.225,81.7 30.225,75.9 30.525,75.6 30.525,74.375 30.225,74.075 30.225,70.375 31.25,69.35
eMMC_SDIO2_D7: U1.B11 U5.B6 | length 20.7
  Top Layer w0.09: U5.B6@29.7,84.975 29.95,85.225 30.325,85.225 30.45,85.1 30.45,83.85 ; U1.B11@31.5,67.7 31.74,67.94 31.74,69.635
  Top Layer w0.13: 30.45,83.85 30.875,83.425 30.875,82.275 31.175,81.975 31.8,81.975 31.925,81.85 31.925,78.375 31.125,77.575 31.125,76.5 31.925,75.7 31.925,74 31.075,73.15 31.075,70.3 31.74,69.635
